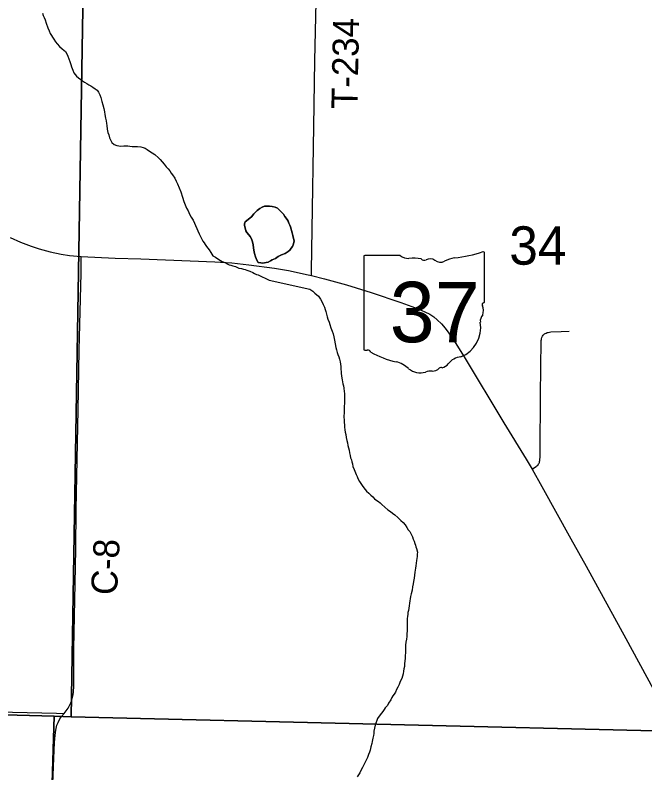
# Model space of a CAD drawing. Extents: x 1587405 to 1714697, y 1028970 to 1155083.
# Drawn here: x 1666331 to 1669958, y 1091803 to 1096169 of the extents above; entities that cross this region are included whole.
import ezdxf

# ---------------------------------------------------------------- set-up
doc = ezdxf.new("R2010")
doc.units = 0
for name, color, linetype in [('GM_X_County_Road', 7, 'Continuous'), ('GM_X_County_Road_Text', 7, 'Continuous'), ('GM_X_Minor_Lake', 7, 'Continuous'), ('GM_X_Minor_River', 7, 'Continuous'), ('GM_X_Section', 7, 'Continuous'), ('GM_X_Section_Text', 7, 'Continuous'), ('GM_X_State_Route', 7, 'Continuous'), ('GM_X_State_Shield', 7, 'Continuous'), ('GM_X_Township_Road', 7, 'Continuous'), ('GM_X_Township_Road_Text', 7, 'Continuous')]:
    doc.layers.add(name, color=color, linetype=linetype)

msp = doc.modelspace()

# ---------------------------------------------------------------- linework, layer by layer
at = {"layer": 'GM_X_County_Road'}
for points in [[(1666614.5, 1092145.3), (1666637.2, 1092175.7), (1666652, 1092205.3), (1666658.1, 1092220.8), (1666665.7, 1092253.2), (1666667.6, 1092269.7), (1666669.8, 1092302.8), (1666669.9, 1092516.6), (1666677.9, 1092893.8), (1666679.9, 1093090.8), (1666683.6, 1093320.4), (1666694.5, 1093894.5), (1666700.9, 1094239.1), (1666712, 1094682), (1666711.6, 1094748), (1666711.4, 1094778.4)], [(1666468.4, 1089539.4), (1666471.6, 1089656.7), (1666483.5, 1090017.4), (1666496.4, 1090394.5), (1666505.4, 1090623.4), (1666518.6, 1090902.9), (1666527.2, 1091148.7), (1666544.5, 1091642.9), (1666553.6, 1091886.4), (1666558.8, 1091977), (1666562.3, 1092020.2), (1666565.8, 1092049.3), (1666571.8, 1092078), (1666578.8, 1092093.1), (1666589.2, 1092113.1), (1666599.1, 1092127.3), (1666614.5, 1092145.3)]]:
    msp.add_lwpolyline(points, dxfattribs=at)
at = {"layer": 'GM_X_Minor_Lake'}
for points in [[(1667655.8, 1094978.3), (1667692.4, 1095005.9), (1667706.7, 1095023.8), (1667725.1, 1095043.7), (1667741.3, 1095055.5), (1667753.5, 1095063.4), (1667767.7, 1095069.2), (1667781.8, 1095069), (1667795.9, 1095068.8), (1667812, 1095066.6), (1667828, 1095062.4), (1667842.1, 1095056.2), (1667858, 1095041.9), (1667867.9, 1095031.8), (1667875.9, 1095021.6), (1667883.8, 1095009.4), (1667897.6, 1094991.2), (1667903.5, 1094981.1), (1667907.5, 1094971), (1667913.3, 1094958.8), (1667917.2, 1094948.7), (1667926.9, 1094914.4), (1667930.7, 1094898.3), (1667934.5, 1094882.2), (1667938.4, 1094868.1), (1667936.2, 1094858.1), (1667932.1, 1094846.1), (1667927.9, 1094836.1), (1667921.7, 1094826.1), (1667913.5, 1094814.2), (1667903.4, 1094806.3), (1667887.1, 1094796.4), (1667864.9, 1094788.7), (1667846.6, 1094778.9), (1667830.4, 1094767.1), (1667812.1, 1094759.2), (1667802, 1094753.4), (1667787.8, 1094745.5), (1667777.7, 1094743.6), (1667757.5, 1094739.9), (1667745.4, 1094742), (1667731.4, 1094744.2), (1667723.5, 1094756.4), (1667719.6, 1094766.5), (1667715.7, 1094776.6), (1667709.9, 1094794.8), (1667708, 1094804.8), (1667706.1, 1094814.9), (1667704.2, 1094829), (1667702.4, 1094845.1), (1667698.6, 1094863.2), (1667692.8, 1094879.3), (1667684.9, 1094893.5), (1667677, 1094903.7), (1667665.1, 1094915.9), (1667659.1, 1094926), (1667657.3, 1094936.1), (1667651.5, 1094956.2), (1667651.6, 1094966.3), (1667655.8, 1094978.3)], [(1667913.5, 1094814.2), (1667921.7, 1094826.1), (1667927.9, 1094836.1), (1667932.1, 1094846.1), (1667936.2, 1094858.1), (1667938.4, 1094868.1), (1667934.5, 1094882.2), (1667930.7, 1094898.3), (1667926.9, 1094914.4), (1667917.2, 1094948.7), (1667913.3, 1094958.8), (1667907.5, 1094971), (1667903.5, 1094981.1), (1667897.6, 1094991.2), (1667883.8, 1095009.4), (1667875.9, 1095021.6), (1667867.9, 1095031.8), (1667858, 1095041.9), (1667842.1, 1095056.2), (1667828, 1095062.4), (1667812, 1095066.6), (1667795.9, 1095068.8), (1667781.8, 1095069), (1667767.7, 1095069.2), (1667753.5, 1095063.4), (1667741.3, 1095055.5), (1667725.1, 1095043.7), (1667706.7, 1095023.8), (1667692.4, 1095005.9), (1667655.8, 1094978.3)], [(1667655.8, 1094978.3), (1667651.6, 1094966.3), (1667651.5, 1094956.2), (1667657.3, 1094936.1), (1667659.1, 1094926), (1667665.1, 1094915.9), (1667677, 1094903.7), (1667684.9, 1094893.5), (1667692.8, 1094879.3), (1667698.6, 1094863.2), (1667702.4, 1094845.1), (1667704.2, 1094829), (1667706.1, 1094814.9), (1667708, 1094804.8), (1667709.9, 1094794.8), (1667715.7, 1094776.6), (1667719.6, 1094766.5), (1667723.5, 1094756.4), (1667731.4, 1094744.2), (1667745.4, 1094742), (1667757.5, 1094739.9), (1667777.7, 1094743.6), (1667787.8, 1094745.5), (1667802, 1094753.4), (1667812.1, 1094759.2), (1667830.4, 1094767.1), (1667846.6, 1094778.9), (1667864.9, 1094788.7), (1667887.1, 1094796.4), (1667903.4, 1094806.3), (1667913.5, 1094814.2)]]:
    msp.add_lwpolyline(points, dxfattribs=at)
at = {"layer": 'GM_X_Minor_River'}
for points in [[(1666488.6, 1096180.9), (1666492.5, 1096166.8), (1666498.3, 1096154.7), (1666504.2, 1096142.5), (1666510, 1096122.4), (1666519.8, 1096096.1), (1666527.6, 1096077.9), (1666533.5, 1096063.8), (1666541.4, 1096051.6), (1666547.3, 1096041.5), (1666553.2, 1096031.4), (1666563.1, 1096015.2), (1666573, 1096003), (1666586.9, 1095988.8), (1666602.8, 1095974.5), (1666620.8, 1095960.2), (1666630.6, 1095942), (1666634.5, 1095931.9), (1666640.4, 1095917.7), (1666646.2, 1095901.6), (1666652.1, 1095885.4), (1666655.9, 1095871.3), (1666659.8, 1095861.2), (1666663.7, 1095851.1), (1666669.6, 1095837), (1666685.4, 1095816.7), (1666695.4, 1095808.5), (1666709.4, 1095798.3), (1666719.3, 1095790.1), (1666731.3, 1095781.9), (1666743.3, 1095775.8), (1666755.3, 1095767.6), (1666767.3, 1095761.4), (1666779.3, 1095753.2), (1666791.3, 1095745), (1666803.3, 1095736.8), (1666811.2, 1095724.6), (1666819, 1095710.5), (1666824.9, 1095694.3), (1666830.6, 1095672.1), (1666836.4, 1095652), (1666842.2, 1095631.8), (1666846, 1095611.7), (1666847.8, 1095595.6), (1666851.6, 1095575.4), (1666855.4, 1095559.3), (1666857.2, 1095545.2), (1666859.1, 1095533.2), (1666860.8, 1095511)], [(1666860.8, 1095511), (1666864.6, 1095492.9), (1666870.5, 1095478.8), (1666874.3, 1095462.6), (1666888.1, 1095434.3), (1666902, 1095424.1), (1666916.1, 1095417.9), (1666928.1, 1095415.7), (1666940.2, 1095413.6), (1666956.3, 1095415.4), (1666968.4, 1095415.2), (1666980.5, 1095415.1), (1666992.6, 1095414.9), (1667004.6, 1095412.7), (1667014.7, 1095412.6), (1667026.8, 1095412.4), (1667036.8, 1095412.3), (1667054.9, 1095410.1), (1667069, 1095405.8), (1667081, 1095401.7), (1667091, 1095395.5), (1667105, 1095385.3), (1667121, 1095375), (1667135, 1095366.8), (1667156.9, 1095346.4), (1667166.8, 1095336.3), (1667178.7, 1095324.1), (1667188.6, 1095309.9), (1667200.5, 1095295.6), (1667212.5, 1095283.4), (1667222.4, 1095271.2), (1667230.3, 1095259.1), (1667238.2, 1095248.9), (1667250, 1095228.7), (1667257.9, 1095212.5), (1667265.8, 1095196.3), (1667275.5, 1095174.1), (1667285.3, 1095149.9), (1667295, 1095119.6), (1667302.8, 1095095.4), (1667310.6, 1095075.2), (1667318.4, 1095057), (1667328.2, 1095040.8), (1667336.1, 1095022.6), (1667345.9, 1095004.4), (1667355.8, 1094988.2), (1667391.1, 1094909.4), (1667402.8, 1094885.2), (1667412.7, 1094866.9), (1667420.6, 1094856.8), (1667426.5, 1094846.7), (1667432.4, 1094836.6), (1667440.4, 1094826.4), (1667448.3, 1094816.3), (1667458.2, 1094802.1), (1667470, 1094781.8), (1667486, 1094773.6), (1667504, 1094761.3), (1667514, 1094755.1), (1667524, 1094749), (1667538, 1094742.8), (1667552, 1094736.5), (1667564, 1094730.4), (1667574.1, 1094728.2), (1667584.1, 1094724.1), (1667600.2, 1094719.8), (1667620.2, 1094711.5), (1667634.3, 1094709.3), (1667646.3, 1094705.2), (1667656.3, 1094703), (1667666.4, 1094698.9), (1667682.4, 1094694.6), (1667700.4, 1094686.4), (1667710.4, 1094680.2), (1667720.4, 1094674.1), (1667730.5, 1094671.9), (1667793.7, 1094642.5)], [(1667793.7, 1094642.5), (1668028.8, 1094589.6), (1668044.8, 1094577.5), (1668056.9, 1094567.4), (1668078.9, 1094549.3), (1668088.9, 1094533.2), (1668096.9, 1094519.1), (1668104.9, 1094501), (1668112.9, 1094487), (1668116.8, 1094472.9), (1668120.8, 1094460.9), (1668124.8, 1094446.8), (1668128.8, 1094430.7), (1668132.8, 1094416.7), (1668138.8, 1094400.6), (1668142.7, 1094386.6), (1668148.7, 1094366.5), (1668156.7, 1094348.4), (1668162.7, 1094332.3), (1668166.7, 1094316.2), (1668170.6, 1094296.2), (1668174.6, 1094274.1), (1668178.6, 1094254), (1668182.5, 1094239.9), (1668186.5, 1094225.9), (1668190.5, 1094213.8), (1668194.5, 1094199.8), (1668198.5, 1094185.7), (1668202.5, 1094171.6), (1668204.4, 1094157.6), (1668206.4, 1094143.5), (1668206.4, 1094129.5), (1668208.3, 1094113.4), (1668208.3, 1094103.4), (1668210.3, 1094091.3), (1668212.3, 1094077.3), (1668214.3, 1094067.3), (1668216.2, 1094055.2), (1668218.2, 1094045.2), (1668222.2, 1094033.1), (1668224.2, 1094019.1), (1668226.1, 1094001), (1668228.1, 1093989), (1668228, 1093954.8), (1668228, 1093944.8), (1668228, 1093932.8), (1668225.9, 1093914.7), (1668225.9, 1093900.7), (1668225.9, 1093882.6), (1668225.8, 1093872.6), (1668223.8, 1093862.6), (1668223.8, 1093850.5), (1668225.8, 1093838.5), (1668225.7, 1093822.4), (1668227.7, 1093808.4), (1668227.7, 1093794.3), (1668229.6, 1093780.3), (1668231.6, 1093766.2), (1668235.6, 1093752.1), (1668237.6, 1093736.1), (1668241.5, 1093718), (1668245.5, 1093704), (1668247.5, 1093689.9), (1668251.5, 1093675.8), (1668255.5, 1093661.8), (1668257.4, 1093647.7), (1668261.4, 1093631.7), (1668263.4, 1093617.6), (1668267.4, 1093605.6), (1668269.4, 1093595.5), (1668273.3, 1093583.5), (1668275.3, 1093567.4), (1668283.3, 1093551.3), (1668287.3, 1093541.3), (1668291.3, 1093531.2), (1668295.3, 1093521.2), (1668301.3, 1093511.1), (1668305.3, 1093499.1), (1668315.3, 1093481), (1668321.2, 1093470.9), (1668329.2, 1093458.9), (1668339.3, 1093444.8), (1668355.3, 1093426.7), (1668367.3, 1093414.6), (1668379.3, 1093402.5), (1668391.3, 1093392.5), (1668401.3, 1093382.4), (1668413.3, 1093372.3), (1668423.4, 1093366.3), (1668433.4, 1093358.2), (1668443.4, 1093348.2), (1668477.4, 1093317.9), (1668493.5, 1093307.9), (1668503.5, 1093299.8), (1668517.5, 1093289.7), (1668535.5, 1093273.6), (1668551.5, 1093257.5), (1668565.6, 1093245.4), (1668577.6, 1093231.3), (1668587.6, 1093217.3), (1668595.6, 1093203.2)], [(1668595.6, 1093203.2), (1668603.6, 1093193.1), (1668611.6, 1093179.1), (1668619.6, 1093163), (1668623.5, 1093148.9), (1668629.5, 1093136.9), (1668633.5, 1093124.8), (1668637.5, 1093114.8), (1668639.5, 1093104.7), (1668643.5, 1093094.7), (1668647.5, 1093074.6), (1668647.4, 1093062.6), (1668647.4, 1093048.5), (1668645.4, 1093038.5), (1668643.3, 1093026.4), (1668641.3, 1093010.4), (1668639.3, 1092996.4), (1668637.2, 1092982.3), (1668635.2, 1092970.3), (1668633.1, 1092958.3), (1668631.1, 1092942.2), (1668629, 1092924.2), (1668625, 1092906.1), (1668623, 1092892.1), (1668618.9, 1092874), (1668616.9, 1092856), (1668612.8, 1092833.9), (1668608.7, 1092819.9), (1668606.7, 1092805.8), (1668604.7, 1092793.8), (1668598.5, 1092751.7), (1668596.5, 1092737.7), (1668592.5, 1092727.6), (1668592.4, 1092717.6), (1668590.4, 1092703.6), (1668588.4, 1092691.5), (1668588.3, 1092669.5), (1668588.3, 1092653.4), (1668588.2, 1092635.3), (1668588.2, 1092621.3), (1668586.2, 1092603.2), (1668586.1, 1092589.2), (1668584.1, 1092573.2), (1668582, 1092555.1), (1668580, 1092539.1), (1668579.9, 1092513), (1668579.9, 1092494.9), (1668577.8, 1092478.9), (1668577.8, 1092462.8), (1668575.8, 1092446.8), (1668573.7, 1092432.7), (1668573.7, 1092414.7), (1668569.7, 1092402.6), (1668567.6, 1092388.6), (1668565.6, 1092372.6), (1668561.5, 1092360.5), (1668557.5, 1092346.5), (1668549.4, 1092328.4), (1668543.4, 1092312.4), (1668535.3, 1092296.4), (1668527.2, 1092282.4), (1668521.2, 1092268.3), (1668513.1, 1092256.3), (1668507.1, 1092246.3), (1668501, 1092236.3), (1668495, 1092224.3), (1668480.9, 1092204.3), (1668474.8, 1092190.2), (1668462.8, 1092178.2), (1668456.7, 1092168.2), (1668448.7, 1092156.2), (1668440.6, 1092146.2), (1668428.5, 1092130.2), (1668418.5, 1092116.2), (1668404.3, 1092078.1), (1668400.3, 1092060.1), (1668396.2, 1092042), (1668396.2, 1092030), (1668394.2, 1092017.9), (1668392.1, 1092001.9), (1668388.1, 1091983.8), (1668386, 1091971.8), (1668380, 1091951.8), (1668375.9, 1091933.7), (1668371.9, 1091921.7), (1668365.8, 1091907.6), (1668359.8, 1091891.6), (1668353.7, 1091875.6), (1668345.6, 1091859.6), (1668337.6, 1091845.5), (1668331.5, 1091833.5), (1668323.5, 1091819.5), (1668315.4, 1091803.5), (1668301.3, 1091779.4)]]:
    msp.add_lwpolyline(points, dxfattribs=at)
at = {"layer": 'GM_X_Section'}
for points in [[(1666741, 1097373.7), (1666653.8, 1092126.1), (1666555.8, 1092129.2), (1661358.4, 1092269.9), (1661429.4, 1097506)], [(1672060.5, 1097231.1), (1671935.5, 1091998.3), (1666653.8, 1092126.1), (1666741, 1097373.7)], [(1661264.4, 1092271), (1661358.4, 1092269.9), (1666555.8, 1092129.2), (1666401.8, 1086987.9), (1660988.4, 1087141.1)], [(1666555.8, 1092129.2), (1666653.8, 1092126.1), (1671935.5, 1091998.3), (1671767.3, 1086851.1), (1666401.8, 1086987.9)]]:
    msp.add_lwpolyline(points, close=True, dxfattribs=at)
at = {"layer": 'GM_X_State_Route'}
for points in [[(1666302.2, 1094887.7), (1666362, 1094860.8), (1666422.8, 1094836.8), (1666469.3, 1094821.5), (1666532.4, 1094804.5), (1666596.5, 1094791.8), (1666645, 1094784.5), (1666711.4, 1094778.4), (1666906.7, 1094769.2), (1667054.4, 1094764.7), (1667481, 1094748.4), (1667579.5, 1094741.4), (1667677.5, 1094730.6), (1667824.1, 1094710.3), (1667905.2, 1094696.7), (1668017.8, 1094672.9), (1668038.4, 1094667.9)], [(1668038.4, 1094667.9), (1668113.6, 1094649.4), (1668240.4, 1094614.3), (1668381.6, 1094570.6), (1668553.2, 1094513.3), (1668615.2, 1094490.8), (1668656.4, 1094475.1), (1668689.8, 1094460.1), (1668719.1, 1094445.1), (1668741.7, 1094430), (1668760.9, 1094414.1), (1668786, 1094389.9), (1668806.9, 1094364.8), (1668827.9, 1094336.4), (1668864.4, 1094283.4), (1668916.8, 1094199.6), (1669146.5, 1093820.5), (1669274.2, 1093609.8), (1669308.1, 1093552.4), (1669365.2, 1093453.7), (1669531.7, 1093151.7), (1669619.1, 1092993.7), (1669848.4, 1092576.4), (1670004.9, 1092287.7)]]:
    msp.add_lwpolyline(points, dxfattribs=at)
at = {"layer": 'GM_X_State_Shield'}
for p, q in [((1668549.1, 1094784.2), (1668345.3, 1094784.2)), ((1669034.5, 1094520.9), (1669034.5, 1094797.3)), ((1668338.4, 1094775.1), (1668338.4, 1094246.8)), ((1669034.4, 1094521), (1669034.5, 1094520.9))]:
    msp.add_line(p, q, dxfattribs=at)
for centre, radius, start, end in [((1668346.4, 1094776.3), 8.06, 98.1301, 188.1301), ((1668597.7, 1094845.5), 78.2, 231.6195, 271.1119), ((1668786.6, 1095504.5), 738.2, 275.8445, 288.9065), ((1669026.8, 1094798.5), 7.75, 351.8621, 97.738), ((1668623.6, 1094487.6), 280.8, 80.4867, 94.9883), ((1668687.4, 1094779), 22.6, 219.7921, 297.1024), ((1668720.5, 1094717.9), 46.9, 54.4667, 119.1411), ((1668781, 1094801.7), 56.4, 233.8562, 294.8282), ((1668880.7, 1094622.9), 148.5, 97.3462, 120.7689), ((1669026.2, 1094519.9), 8.29, 289.6038, 7.7341), ((1669032.7, 1094500.7), 12, 107.944, 210.337), ((1668956.4, 1094465.7), 72, 340.033, 23.6496), ((1669062.3, 1094405.3), 52.4, 136.8065, 186.9296), ((1668827.9, 1094370.1), 184.6, 292.3089, 8.9858), ((1668346.5, 1094245.7), 8.14, 171.9584, 258.3066), ((1668347.7, 1094299.7), 62.1, 267.339, 280.6039), ((1668360.4, 1094216.3), 22.4, 29.7484, 93.2717), ((1668643, 1094691), 533.1, 240.4129, 257.1985), ((1668484.1, 1094009.5), 166.8, 47.1842, 75.836), ((1668905.8, 1094098.5), 101.1, 94.4031, 142.5768), ((1668664.5, 1094213.7), 105.8, 230.7004, 286.2918), ((1668733.4, 1094174.1), 56.4, 268.777, 315.5493), ((1668784.4, 1094123), 15.9, 65.7517, 132.6484), ((1668777.6, 1094195.6), 59.7, 282.8732, 323.2771), ((1668725.7, 1094031), 87, 85.6951, 111.2099)]:
    msp.add_arc(centre, radius, start, end, dxfattribs=at)
at = {"layer": 'GM_X_Township_Road'}
for points in [[(1668038.4, 1094667.9), (1668038.7, 1094695.3), (1668041.6, 1094936.4), (1668051.6, 1095527.3), (1668058.1, 1095904.9), (1668066.6, 1096331.7), (1668082.7, 1097201.7), (1668084.7, 1097398.8), (1668088.6, 1097595.7), (1668095.9, 1098121), (1668098.9, 1098235.9), (1668098.4, 1098288.5)], [(1669308.1, 1093552.4), (1669323, 1093561.6), (1669331.6, 1093567.5), (1669335.6, 1093571), (1669340.5, 1093576), (1669342.7, 1093578.6), (1669346.1, 1093583.5), (1669348.2, 1093586.9), (1669350.2, 1093591.8), (1669351.6, 1093596.1), (1669352.8, 1093602.1), (1669353.7, 1093610.1), (1669354.3, 1093619.7), (1669354.3, 1093631.1), (1669355.4, 1093668.2), (1669355.4, 1093686.9), (1669355.7, 1093756.9), (1669357, 1093874.5), (1669357.2, 1093966.4), (1669358.8, 1094150.1), (1669360.8, 1094281.4), (1669361.2, 1094291), (1669361.4, 1094294.5), (1669362, 1094300.6), (1669362.8, 1094304.7), (1669364.5, 1094311.1), (1669365.9, 1094315), (1669368, 1094319.2), (1669371.7, 1094324.6), (1669375.9, 1094328.8), (1669379.4, 1094331.9), (1669383.6, 1094334.7), (1669388.5, 1094337.2), (1669394.6, 1094339.3), (1669400.9, 1094341.1), (1669408.4, 1094342.6), (1669417.1, 1094343.4), (1669476.2, 1094346.3), (1669522.3, 1094347.9)], [(1664008.6, 1092205.3), (1664727, 1092192), (1665284.6, 1092177.8), (1665891.5, 1092161.5), (1666570.1, 1092146.3), (1666614.5, 1092145.3)]]:
    msp.add_lwpolyline(points, dxfattribs=at)

# ---------------------------------------------------------------- texts
at = {"layer": 'GM_X_County_Road_Text'}
msp.add_text('C-8', height=150, rotation=86.9706, dxfattribs=at).set_placement((1666917.2, 1092824.4))
at = {"layer": 'GM_X_Section_Text'}
msp.add_text('34', height=221, rotation=0, dxfattribs=at).set_placement((1669177.1, 1094731))
at = {"layer": 'GM_X_State_Shield'}
msp.add_text('37', height=348.05, dxfattribs=at).set_placement((1668488.6, 1094284.1))
at = {"layer": 'GM_X_Township_Road_Text'}
msp.add_text('T-234', height=150, rotation=88.8724, dxfattribs=at).set_placement((1668302.2, 1095627.2))

doc.saveas('drawing.dxf')
